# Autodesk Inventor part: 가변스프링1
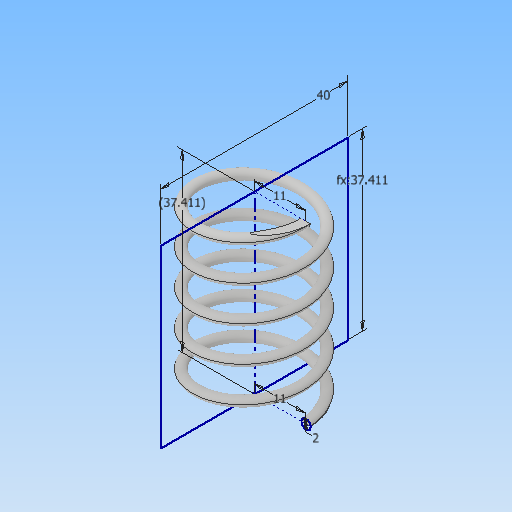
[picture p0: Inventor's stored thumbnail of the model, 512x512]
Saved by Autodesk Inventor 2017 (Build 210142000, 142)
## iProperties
Part Number: 가변스프링1
Material: 일반
Document SubType Name: Modeling
Designer: MRC
Density: 1 g/cm^3
Appearance: 기본값
Mass: 1.07319 g
Surface Area: 21.7273 cm^2
Volume: 1.07319 cm^3
Author: MRC
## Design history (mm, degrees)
sketch "스케치1"
  geometry: L1 (0, 0)-(0, 37.411); L2 (0, 0)-(11, 0); L3 (0, 37.411)-(11, 37.411); C1 r 1 at (11, 0)
  constraints: 6 end point, 2 horizontal, 1 centre point, 1 coincident, 1 vertical
  dimensions: "d0" = 11 distance of L1.start L2.end; "d1" = 11 distance of L1.end L3.end; "d2" = 2 diameter of C1; "d3" = 37.4112 distance of L1.start L1.end (derived)
feature "코일1" sketch "스케치1" pitch "d4" = 10; turns "d6" = 5; dims "d5" = 37.4112 (= d3), "d7" = 0, angle "d8" = 90 deg, angle "d9" = 90 deg, "d10" = 0, "d11" = 0
sketch "스케치2"
  geometry: L1 (37.411, 20)-(0, 20); L2 (0, 20)-(0, -20); L3 (0, -20)-(37.411, -20); L4 (37.411, -20)-(37.411, 20); 2 further points
  constraints: 8 end point, 2 parallel, 1 coincident, 1 horizontal, 1 midpoint, 1 perpendicular
  dimensions: "d13" = 37.4112 distance of L2.end L3.end (= d3); "d14" = 40 distance of L3.end L1.start
extrude "돌출1" sketch "스케치2" stored distance "d15" = 0; taper "d16" = 0 deg
node "솔리드1"
